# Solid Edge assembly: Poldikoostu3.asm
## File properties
Author: Türk
Template: Iso Assembly.asm
Last saved by: Türk
Revision: 3
Application: Solid Edge
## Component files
Polt59,5x20.par
Mutter.par
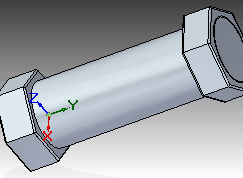
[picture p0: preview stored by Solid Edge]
